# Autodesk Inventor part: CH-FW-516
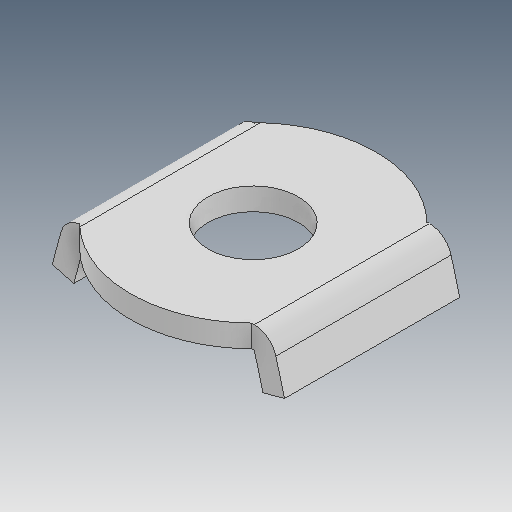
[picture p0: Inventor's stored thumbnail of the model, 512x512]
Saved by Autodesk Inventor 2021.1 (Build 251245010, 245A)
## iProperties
Created: 2020-03
Part Number: CH-FW-516
Material: Ogólny
Document SubType Name: Modeling
Designer: user
Density: 1 g/cm^3
Appearance: Domyślna
Author: user
Revision Number: ÈÎºÎ
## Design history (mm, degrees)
feature "ÇÐ³ý-À­Éì3"
node "Bryła1"
